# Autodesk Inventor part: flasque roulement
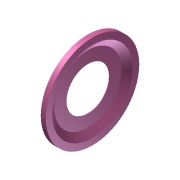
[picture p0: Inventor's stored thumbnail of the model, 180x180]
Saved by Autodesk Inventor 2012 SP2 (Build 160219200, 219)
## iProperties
Created: 2013-04
Part Number: flasque roulement
Material: Default
Document SubType Name: Modeling
Designer: papa
Density: 1 g/cm^3
Mass: 0.221452 g
Surface Area: 22.4845 cm^2
Volume: 0.221452 cm^3
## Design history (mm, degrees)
node "flasque roulement1"
node "flasque roulement"
node "Base1"
